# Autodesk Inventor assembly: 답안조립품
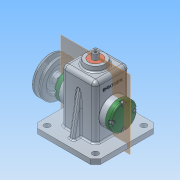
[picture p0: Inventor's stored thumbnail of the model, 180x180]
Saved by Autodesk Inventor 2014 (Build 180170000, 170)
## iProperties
Created: 2016-02
Part Number: 답안조립품
Document SubType Name: Assembly
Designer: nert
Author: nert
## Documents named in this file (16)
- C:\Users\nert\Desktop\460211V1011\답안조립품.iam
- C:\Users\nert\Desktop\460211V1011\본체.ipt
- C:\Users\nert\Desktop\460211V1011\뒤커버.ipt
- C:\Users\nert\Desktop\460211V1011\베어링 12 x 32 x 10.ipt
- C:\Users\nert\Desktop\460211V1011\앞커버.ipt
- C:\Users\nert\Desktop\460211V1011\편심축.ipt
- C:\Users\nert\Desktop\460211V1011\키 4 x 4 x 10.ipt
- C:\Users\nert\Desktop\460211V1011\부시.ipt
- C:\Users\nert\Desktop\460211V1011\슬라이드.ipt
- C:\Users\nert\Desktop\460211V1011\핀 5 x 18.ipt
- C:\Users\nert\Desktop\460211V1011\고정핀 1.2 x 10.ipt
- C:\Users\nert\Desktop\460211V1011\V벨트풀리.ipt
- C:\Users\nert\Desktop\460211V1011\오일실 12 25 7.ipt
- C:\Users\nert\Desktop\460211V1011\링크.ipt
- C:\Users\nert\Desktop\460211V1011\멈춤나사 M3x8.ipt
- C:\Users\nert\Desktop\460211V1011\볼트 M4 x 12.ipt
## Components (11 placed, 4 different names)
1. 핀 5 x 18:2 — 강체:1
2. 고정핀 1.2 x 10:1 — 강체:1
3. V벨트풀리:1 — 각도:1
4. ISO 4762 M4 x 12:2
5. ISO 4762 M4 x 12:3
6. ISO 4762 M4 x 12:4
7. ISO 4762 M4 x 12:5
8. ISO 4762 M4 x 12:1
9. ISO 4762 M4 x 12:6
10. ISO 4762 M4 x 12:7
11. ISO 4762 M4 x 12:8
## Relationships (2: Angle 1, WeldJoint 1)
- 각도:1 [Angle]: V벨트풀리:1
- 강체:1 [WeldJoint]: 핀 5 x 18:2 ↔ 고정핀 1.2 x 10:1
